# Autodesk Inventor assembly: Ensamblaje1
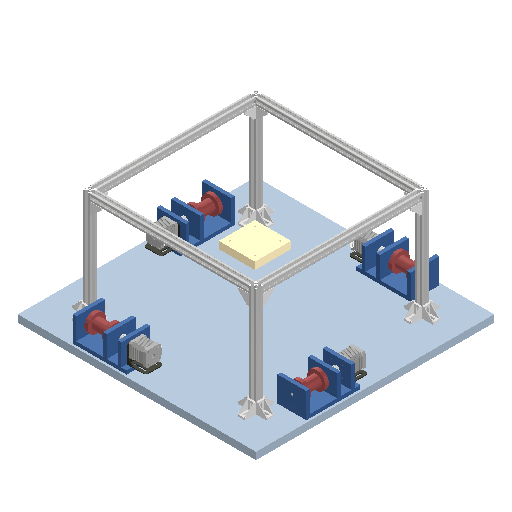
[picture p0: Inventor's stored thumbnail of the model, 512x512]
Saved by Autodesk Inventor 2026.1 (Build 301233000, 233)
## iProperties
Created: 2025-06
Part Number: Ensamblaje1
Document SubType Name: Assembly
Designer: piero
Author: piero
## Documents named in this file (7)
- D:\Tesis\Modelo 3D\CAD\Ensamblaje1.iam
- D:\Tesis\Modelo 3D\CAD\Mesa.ipt
- D:\Tesis\Modelo 3D\CAD\V-slot.ipt
- D:\Tesis\Modelo 3D\CAD\Ensamblaje2.iam
- D:\Tesis\Modelo 3D\CAD\Plataforma.ipt
- D:\Tesis\Modelo 3D\CAD\Esquinero.ipt
- D:\Tesis\Modelo 3D\CAD\V-slot_2.ipt
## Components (38 placed, 6 different names)
1. Mesa:1
2. V-slot:1
3. V-slot:2 — Nivelación:9, Nivelación:10, Coincidencia:5, Coincidencia:6, Nivelación:11, Nivelación:12
4. V-slot:3 — Coincidencia:7, Coincidencia:8, Coincidencia:9
5. V-slot:4 — Nivelación:1, Nivelación:2, Coincidencia:1, Nivelación:3, Nivelación:4, Coincidencia:2, Coincidencia:10
6. Plataforma:1
7. V-slot_2:1
8. V-slot_2:2 — Nivelación:1, Nivelación:2, Coincidencia:1, Coincidencia:8, Coincidencia:9
9. V-slot_2:3 — Coincidencia:6, Nivelación:11, Nivelación:12, Coincidencia:7
10. V-slot_2:4
11. Esquinero:6 — Coincidencia:13, Nivelación:14, Coincidencia:14
12. Esquinero:5 — Coincidencia:11, Nivelación:13, Coincidencia:12
13. Ensamblaje2:1 [sub-assembly] — Coincidencia:22
14. Esquinero:11
15. Esquinero:12
16. Ensamblaje2:2 [sub-assembly]
17. Esquinero:17
18. Esquinero:18
19. Ensamblaje2:3 [sub-assembly]
20. Esquinero:23
21. Esquinero:24
22. Ensamblaje2:4 [sub-assembly]
23. Esquinero:7 — Coincidencia:25, Nivelación:15, Coincidencia:26
24. Esquinero:8
25. Esquinero:9
26. Esquinero:10
27. Esquinero:13
28. Esquinero:14
29. Esquinero:15
30. Esquinero:16
31. Esquinero:19
32. Esquinero:20
33. Esquinero:21
34. Esquinero:22
35. Esquinero:25
36. Esquinero:26
37. Esquinero:27
38. Esquinero:28
## Component patterns: Patrón de componentes 2:2 (4 elements), Patrón de componentes 2:3 (4 elements), Patrón de componentes 2:4 (4 elements)
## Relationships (26: Mate 15, Flush 11)
- Nivelación:1 [Flush]: V-slot:4 ↔ V-slot_2:2
- Nivelación:2 [Flush]: V-slot:4 ↔ V-slot_2:2
- Coincidencia:1 [Mate]: V-slot:4 ↔ V-slot_2:2
- Nivelación:3 [Flush]: V-slot:4
- Nivelación:4 [Flush]: V-slot:4
- Coincidencia:2 [Mate]: V-slot:4
- Nivelación:9 [Flush]: V-slot:2
- Nivelación:10 [Flush]: V-slot:2
- Coincidencia:5 [Mate]: V-slot:2
- Coincidencia:6 [Mate]: V-slot:2 ↔ V-slot_2:3
- Nivelación:11 [Flush]: V-slot:2 ↔ V-slot_2:3
- Nivelación:12 [Flush]: V-slot:2 ↔ V-slot_2:3
- Coincidencia:7 [Mate]: V-slot:3 ↔ V-slot_2:3
- Coincidencia:8 [Mate]: V-slot:3 ↔ V-slot_2:2
- Coincidencia:9 [Mate]: V-slot:3 ↔ V-slot_2:2
- Coincidencia:10 [Mate]: V-slot:4
- Coincidencia:11 [Mate]: Esquinero:5
- Nivelación:13 [Flush]: Esquinero:5
- Coincidencia:12 [Mate]: Esquinero:5
- Coincidencia:13 [Mate]: Esquinero:6
- Nivelación:14 [Flush]: Esquinero:6
- Coincidencia:14 [Mate]: Esquinero:6
- Coincidencia:22 [Mate]: Ensamblaje2:1
- Coincidencia:25 [Mate]: Esquinero:7
- Nivelación:15 [Flush]: Esquinero:7
- Coincidencia:26 [Mate]: Esquinero:7
